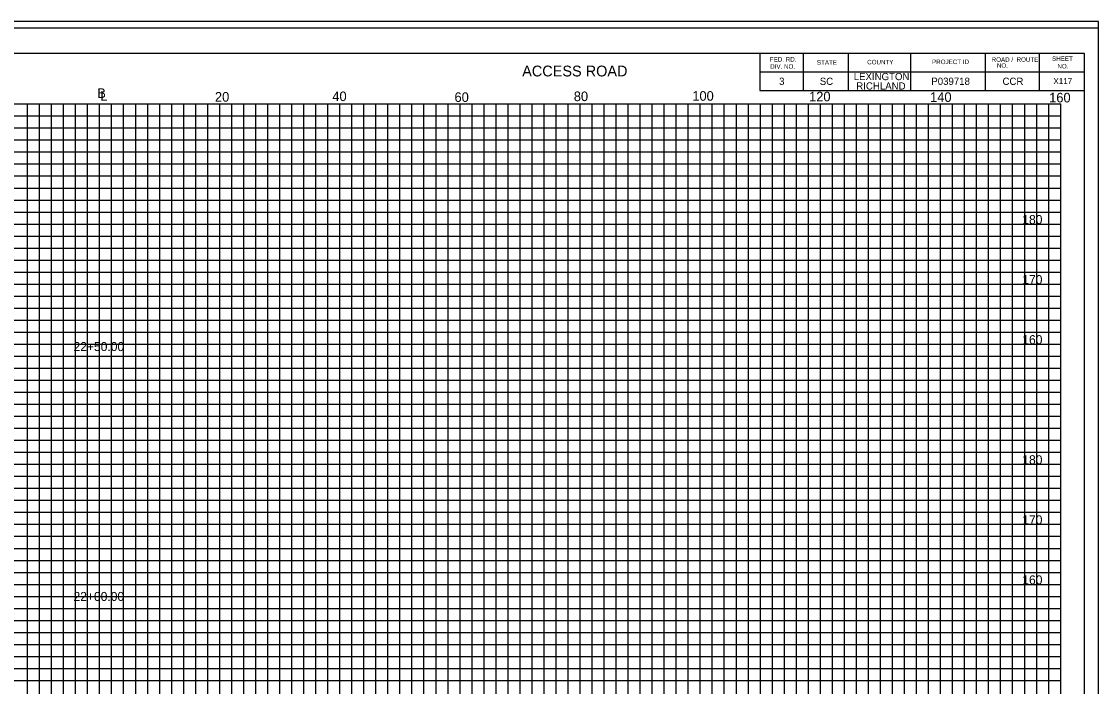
# Model space of a CAD drawing. Extents: x 967 to 1326, y 964 to 2864.
# Drawn here: x 1147 to 1326.3, y 1913 to 2023.7 of the extents above; entities that cross this region are included whole.
import ezdxf

# ---------------------------------------------------------------- set-up
doc = ezdxf.new("R2010")
doc.units = 0
for name, color, linetype in [('Default', 7, 'Continuous'), ('RD_EX_RW', 7, 'Continuous'), ('RD_PD_Final_TX', 7, 'Continuous'), ('RD_SHT_ShtClip', 7, 'Continuous'), ('RD_XS_TX_Elev_PR', 7, 'Continuous'), ('RD_XS_TX_Slope', 7, 'Continuous')]:
    doc.layers.add(name, color=color, linetype=linetype)

msp = doc.modelspace()

# ---------------------------------------------------------------- linework, layer by layer
at = {"layer": 'RD_EX_RW'}
for p, q in [((1000, 2010), (1320, 2010)), ((1150, 1840), (1150, 2010)), ((1160, 1840), (1160, 2010)), ((1170, 1840), (1170, 2010)), ((1180, 1840), (1180, 2010)), ((1190, 1840), (1190, 2010)), ((1200, 1840), (1200, 2010)), ((1210, 1840), (1210, 2010)), ((1220, 1840), (1220, 2010)), ((1230, 1840), (1230, 2010)), ((1240, 1840), (1240, 2010)), ((1250, 1840), (1250, 2010)), ((1260, 1840), (1260, 2010)), ((1270, 1840), (1270, 2010)), ((1280, 1840), (1280, 2010)), ((1290, 1840), (1290, 2010)), ((1300, 1840), (1300, 2010)), ((1310, 1840), (1310, 2010)), ((1320, 1840), (1320, 2010)), ((1000, 2000), (1320, 2000)), ((1000, 1990), (1320, 1990)), ((1000, 1980), (1320, 1980)), ((1000, 1970), (1320, 1970)), ((1000, 1960), (1320, 1960)), ((1000, 1950), (1320, 1950)), ((1000, 1940), (1320, 1940)), ((1000, 1930), (1320, 1930)), ((1000, 1920), (1320, 1920))]:
    msp.add_line(p, q, dxfattribs=at)
at = {"layer": 'RD_PD_Final_TX'}
for p, q in [((996.11, 2018.46), (1323.89, 2018.46)), ((1269.89, 2018.46), (1269.89, 2012.21)), ((1277.14, 2018.46), (1277.14, 2012.21)), ((1284.64, 2018.46), (1284.64, 2012.21)), ((1295, 2018.46), (1295, 2012.21)), ((1307.43, 2018.46), (1307.43, 2012.21)), ((1316.39, 2018.46), (1316.39, 2012.21)), ((1323.89, 2018.46), (1323.89, 1808.98)), ((1269.89, 2015.33), (1323.89, 2015.33)), ((1269.89, 2012.21), (1323.89, 2012.21))]:
    msp.add_line(p, q, dxfattribs=at)
at = {"layer": 'RD_SHT_ShtClip'}
for p, q in [((1148, 1840), (1148, 2010)), ((1152, 1840), (1152, 2010)), ((1154, 1840), (1154, 2010)), ((1156, 1840), (1156, 2010)), ((1158, 1840), (1158, 2010)), ((1162, 1840), (1162, 2010)), ((1164, 1840), (1164, 2010)), ((1166, 1840), (1166, 2010)), ((1168, 1840), (1168, 2010)), ((1172, 1840), (1172, 2010)), ((1174, 1840), (1174, 2010)), ((1176, 1840), (1176, 2010)), ((1178, 1840), (1178, 2010)), ((1182, 1840), (1182, 2010)), ((1184, 1840), (1184, 2010)), ((1186, 1840), (1186, 2010)), ((1188, 1840), (1188, 2010)), ((1192, 1840), (1192, 2010)), ((1194, 1840), (1194, 2010)), ((1196, 1840), (1196, 2010)), ((1198, 1840), (1198, 2010)), ((1202, 1840), (1202, 2010)), ((1204, 1840), (1204, 2010)), ((1206, 1840), (1206, 2010)), ((1208, 1840), (1208, 2010)), ((1212, 1840), (1212, 2010)), ((1214, 1840), (1214, 2010)), ((1216, 1840), (1216, 2010)), ((1218, 1840), (1218, 2010)), ((1222, 1840), (1222, 2010)), ((1224, 1840), (1224, 2010)), ((1226, 1840), (1226, 2010)), ((1228, 1840), (1228, 2010)), ((1232, 1840), (1232, 2010)), ((1234, 1840), (1234, 2010)), ((1236, 1840), (1236, 2010)), ((1238, 1840), (1238, 2010)), ((1242, 1840), (1242, 2010)), ((1244, 1840), (1244, 2010)), ((1246, 1840), (1246, 2010)), ((1248, 1840), (1248, 2010)), ((1252, 1840), (1252, 2010)), ((1254, 1840), (1254, 2010)), ((1256, 1840), (1256, 2010)), ((1258, 1840), (1258, 2010)), ((1262, 1840), (1262, 2010)), ((1264, 1840), (1264, 2010)), ((1266, 1840), (1266, 2010)), ((1268, 1840), (1268, 2010)), ((1272, 1840), (1272, 2010)), ((1274, 1840), (1274, 2010)), ((1276, 1840), (1276, 2010)), ((1278, 1840), (1278, 2010)), ((1282, 1840), (1282, 2010)), ((1284, 1840), (1284, 2010)), ((1286, 1840), (1286, 2010)), ((1288, 1840), (1288, 2010)), ((1292, 1840), (1292, 2010)), ((1294, 1840), (1294, 2010)), ((1296, 1840), (1296, 2010)), ((1298, 1840), (1298, 2010)), ((1302, 1840), (1302, 2010)), ((1304, 1840), (1304, 2010)), ((1306, 1840), (1306, 2010)), ((1308, 1840), (1308, 2010)), ((1312, 1840), (1312, 2010)), ((1314, 1840), (1314, 2010)), ((1316, 1840), (1316, 2010)), ((1318, 1840), (1318, 2010)), ((1000, 2008), (1320, 2008)), ((1000, 2006), (1320, 2006)), ((1000, 2004), (1320, 2004)), ((1000, 2002), (1320, 2002)), ((1000, 1998), (1320, 1998)), ((1000, 1996), (1320, 1996)), ((1000, 1994), (1320, 1994)), ((1000, 1992), (1320, 1992)), ((1000, 1988), (1320, 1988)), ((1000, 1986), (1320, 1986)), ((1000, 1984), (1320, 1984)), ((1000, 1982), (1320, 1982)), ((1000, 1978), (1320, 1978)), ((1000, 1976), (1320, 1976)), ((1000, 1974), (1320, 1974)), ((1000, 1972), (1320, 1972)), ((1000, 1968), (1320, 1968)), ((1000, 1966), (1320, 1966)), ((1000, 1964), (1320, 1964)), ((1000, 1962), (1320, 1962)), ((1000, 1958), (1320, 1958)), ((1000, 1956), (1320, 1956)), ((1000, 1954), (1320, 1954)), ((1000, 1952), (1320, 1952)), ((1000, 1948), (1320, 1948)), ((1000, 1946), (1320, 1946)), ((1000, 1944), (1320, 1944)), ((1000, 1942), (1320, 1942)), ((1000, 1938), (1320, 1938)), ((1000, 1936), (1320, 1936)), ((1000, 1934), (1320, 1934)), ((1000, 1932), (1320, 1932)), ((1000, 1928), (1320, 1928)), ((1000, 1926), (1320, 1926)), ((1000, 1924), (1320, 1924)), ((1000, 1922), (1320, 1922)), ((1000, 1918), (1320, 1918)), ((1000, 1916), (1320, 1916)), ((1000, 1914), (1320, 1914))]:
    msp.add_line(p, q, dxfattribs=at)
at = {"layer": 'RD_XS_TX_Elev_PR'}
for points in [[(967.41, 1803.72), (1326.28, 1803.72), (1326.28, 2023.72), (967.41, 2023.72)], [(988.52, 1804.84), (1326.28, 1804.84), (1326.28, 2022.6), (988.52, 2022.6)]]:
    msp.add_lwpolyline(points, close=True, dxfattribs=at)

# ---------------------------------------------------------------- texts
at = {"layer": 'Default'}
for s, height, p in [('X117', 1, (1318.79, 2013.3)), ('180', 1.5, (1313.61, 1990)), ('170', 1.5, (1313.61, 1980)), ('22+50.00', 1.5, (1155.66, 1968.85)), ('160', 1.5, (1313.61, 1970)), ('180', 1.5, (1313.61, 1950)), ('170', 1.5, (1313.61, 1940)), ('160', 1.5, (1313.61, 1930)), ('22+00.00', 1.5, (1155.66, 1927.24))]:
    msp.add_text(s, height=height, dxfattribs=at).set_placement(p)
at = {"layer": 'RD_XS_TX_Slope'}
for s, height, p in [('FED. RD.', 0.75, (1271.58, 2017.05)), ('STATE', 0.75, (1279.41, 2016.53)), ('COUNTY', 0.75, (1287.78, 2016.59)), ('PROJECT ID', 0.75, (1298.58, 2016.63)), ('ROAD /  ROUTE', 0.75, (1308.51, 2017.01)), ('SHEET', 0.75, (1318.56, 2017.16)), ('DIV. NO.', 0.75, (1271.64, 2015.86)), ('LEXINGTON', 1.2, (1285.54, 2013.96)), ('   NO.', 0.75, (1308.51, 2016.03)), ('NO.', 0.75, (1319.45, 2015.91)), ('3', 1.2, (1273.12, 2013.17)), ('SC', 1.2, (1279.89, 2013.17)), ('RICHLAND', 1.2, (1285.97, 2012.39)), ('P039718', 1.2, (1298.46, 2013.17)), ('CCR', 1.2, (1310.31, 2013.17)), ('B', 1.6, (1159.61, 2010.99)), ('L', 1.6, (1160.12, 2010.54)), ('20', 1.6, (1179.2, 2010.38)), ('40', 1.6, (1198.74, 2010.47)), ('60', 1.6, (1219.08, 2010.33)), ('80', 1.6, (1238.94, 2010.47)), ('100', 1.6, (1258.67, 2010.53)), ('120', 1.6, (1278.11, 2010.43)), ('140', 1.6, (1298.26, 2010.34)), ('160', 1.6, (1318.08, 2010.25))]:
    msp.add_text(s, height=height, dxfattribs=at).set_placement(p)
msp.add_text('ACCESS ROAD', height=1.8, rotation=0, dxfattribs=at).set_placement((1230.35, 2014.58))

doc.saveas('drawing.dxf')
